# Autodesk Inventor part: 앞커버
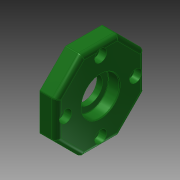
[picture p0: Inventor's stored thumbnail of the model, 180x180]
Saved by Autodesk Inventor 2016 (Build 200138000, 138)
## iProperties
Created: 2015-11
Part Number: 앞커버
Material: 알루미늄 6061
Document SubType Name: Modeling
Designer: mduedu
Density: 1 g/cm^3
Appearance: 매끄러움 - 짙은 산림 녹색
Author: mduedu
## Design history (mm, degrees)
sketch "스케치5" dims "d66" = 58
  geometry: L1 (12.012, 29)-(29, 12.012); L2 (29, 12.012)-(29, -12.012); L3 (29, -12.012)-(12.012, -29); L4 (12.012, -29)-(-12.012, -29); L5 (-12.012, -29)-(-29, -12.012); L6 (-29, -12.012)-(-29, 12.012); L7 (-29, 12.012)-(-12.012, 29); L8 (-12.012, 29)-(12.012, 29); 4 further points
  constraints: 16 end point, 2 coincident, 2 vertical alignment, 1 midpoint, 19 other
extrude "돌출2" new body sketch "스케치5" distance "d67" = 11; taper "d68" = 0 deg
sketch "스케치6"
  geometry: C1 r 16 at (0, 0); 1 further point
  constraints: 1 centre point, 1 coincident
  dimensions: "d69" = 32 diameter of C1
extrude "돌출3" join sketch "스케치6" distance "d70" = 3; taper "d71" = 0 deg
hole "구멍7" diameter "d98" = 28; stored, may be unused: countersink angle "d102" = 90 deg, drill point angle "d104" = 0 deg; dims "d99" = 6, "d100" = 4, "d101" = 2, "d103" = 3, "d145" = 10, "d146" = 10
hole "구멍8" diameter "d107" = 25; stored, may be unused: countersink angle "d111" = 90 deg, drill point angle "d113" = 0 deg; dims "d108" = 6, "d109" = 4, "d110" = 2, "d112" = 7.3, "d143" = 10, "d144" = 10
hole "구멍9" diameter "d116" = 17; stored, may be unused: countersink angle "d120" = 90 deg, drill point angle "d122" = 0 deg; dims "d114" = 10, "d115" = 10, "d117" = 6, "d118" = 4, "d119" = 2, "d121" = 7.7
chamfer "모따기2" distance "d123" = 0.6; stored, may be unused: second distance "d124" = 2, angle "d125" = 30 deg
fillet "모깎기11" dims "d126" = 0.3
fillet "모깎기12" dims "d127" = 1
fillet "모깎기13" dims "d128" = 3
fillet "모깎기14" dims "d129" = 3
fillet "모깎기15" dims "d130" = 0.3
sketch "스케치8" dims "d131" = 46
  geometry: 3 further points
  constraints: 2 vertical alignment, 1 coincident, 2 other
hole "구멍10" sketch "스케치8" at (0, 23) diameter "d132" = 4.5; stored, may be unused: countersink angle "d136" = 90 deg, drill point angle "d138" = 0 deg; dims "d133" = 6, "d134" = 8, "d135" = 4.6, "d137" = 7.7
node "솔리드2"
pattern_circular "원형 패턴4" dims angle "d140" = 360 deg
